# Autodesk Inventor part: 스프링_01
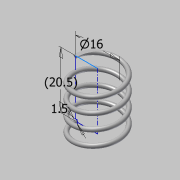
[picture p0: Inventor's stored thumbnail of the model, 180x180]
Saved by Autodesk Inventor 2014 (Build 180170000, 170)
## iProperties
Created: 2015-07
Part Number: 스프링_01
Material: 강철, 연강
Document SubType Name: Modeling
Designer: Administrator
Density: 7.86 g/cm^3
Appearance: 강철
Mass: 2.70743 g
Surface Area: 9.40659 cm^2
Volume: 0.344457 cm^3
Author: Administrator
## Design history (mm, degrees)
sketch "스케치1"
  geometry: L1 (0, 0)-(8, 0); L2 (8, 0)-(8, 10.5); L3 (8, 10.5)-(0, 10.5); L4 (0, 10.5)-(0, 0); C1 r 0.75 at (8, 0)
  constraints: 8 end point, 2 parallel, 1 centre point, 1 coincident, 1 horizontal, 1 perpendicular
  dimensions: "d0" = 10.5 distance between parallel lines of L1 L3 (derived); "d1" = 16 diameter of L2 L4; "d2" = 1.5 diameter of C1
feature "코일1" pitch "d3" = 10; turns "d5" = 4; dims "d4" = 10.5 (= d0), "d6" = 0, angle "d7" = 90 deg, angle "d8" = 90 deg, "d9" = 0, "d10" = 0
node "작업 평면1"
sketch "스케치2"
  geometry: L1 (-0.75, 0)-(0.75, 0) reference; 1 further point
  constraints: 1 horizontal alignment
extrude "돌출1" cut sketch "스케치2" stored distance "d12" = 10; taper "d13" = 0 deg
node "작업 평면2"
sketch "스케치3"
  geometry: L1 (7.25, 0)-(8.75, 0) reference; 1 further point
  constraints: 1 horizontal alignment
extrude "돌출2" cut sketch "스케치3" stored distance "d15" = 10; taper "d16" = 0 deg
node "솔리드1"
node "절단 모서리 투영1"
node "절단 모서리 투영2"
other parameters: "d11" = 90 deg, "d14" = 90 deg
